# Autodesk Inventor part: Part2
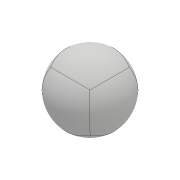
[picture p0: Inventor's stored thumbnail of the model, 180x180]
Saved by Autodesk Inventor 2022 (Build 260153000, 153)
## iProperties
Created: 2015-07
Part Number: Part2
Material: Generic
Document SubType Name: Modeling
Designer: Sandeep
Density: 1 g/cm^3
Appearance: Default
Author: Sandeep
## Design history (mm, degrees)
feature "Form1"
body "Solid1"
